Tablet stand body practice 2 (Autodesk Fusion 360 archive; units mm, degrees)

design "mm-Tablet stand body practice 2" references "haas minimill"
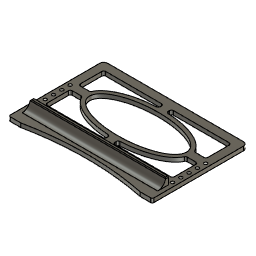
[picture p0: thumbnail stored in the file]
sketch "Sketch1" plane through (0, 0, 0) normal (0, 0, 1) x axis (1, 0, 0)
  line L1 (225.425, 0) -> (0, 0)
  line L2 (225.425, 149.225) -> (225.425, 0)
  line L3 (0, 149.225) -> (225.425, 149.225)
  line L4 (0, 0) -> (0, 149.225)
  point P1 (0, 0)
  point P2 (0, 0)
  point P3 (225.425, 0)
  point P5 (0, 149.225)
  horizontal L1
  vertical L2
  horizontal L3
  vertical L4
  coincident P1 P2
  dimension "d1" distance P2 P3 = 225.425
  dimension "d2" distance P2 P5 = 149.225
extrude "Extrude1" new body sketch "Sketch1" along normal blind 6.35
sketch "Sketch2" plane through (225.425, 0, 0) normal (1, 0, 0) x axis (0, 1, 0)
  line L1 (149.225, 0) -> (0, 0)
  line L2 (149.225, 6.35) -> (149.225, 0)
  line L3 (0, 6.35) -> (149.225, 6.35)
  line L4 (0, 0) -> (0, 6.35)
  line L5 (15.875, 6.35) -> (0, 6.35)
  line L6 (28.575, 6.35) -> (15.875, 6.35)
  line L7 (28.575, 17.907) -> (28.575, 6.35)
  line L8 (31.75, 17.907) -> (28.575, 17.907)
  line L9 (31.75, 6.35) -> (31.75, 17.907)
  line L10 (28.575, 6.35) -> (31.75, 6.35)
  line L11 (27.305, 6.35) -> (28.575, 6.35)
  line L12 (27.305, 16.637) -> (27.305, 6.35)
  line L13 (27.305, 16.637) -> (28.575, 17.907)
  line L14 (34.0111, 17.907) -> (28.575, 17.907)
  point P5 (0, 6.35)
  point P6 (0, 6.35)
  point P11 (31.75, 6.35)
  point P7 (15.875, 6.35)
  point P8 (28.575, 6.35)
  point P9 (28.575, 17.907)
  point P10 (31.75, 17.907)
  point P12 (27.305, 6.35)
  coincident P5 P6
  perpendicular L4 L5
  parallel L3 L6
  perpendicular L6 L7
  perpendicular L7 L8
  coincident L3 P11
  perpendicular L3 L9
  perpendicular L7 L11
  perpendicular L6 L12
  horizontal L14
  dimension "d5" distance P6 P7 = 15.875
  dimension "d6" distance P7 P8 = 12.7
  dimension "d8" distance P8 P9 = 11.557
  dimension "d9" distance P9 P10 = 3.175
  dimension "d10" distance P8 P12 = 1.27
  dimension "d11" angle L13 L14 = 135
extrude "Extrude2" add sketch "Sketch2" profile of L3 L6 L7 L8 L9 L10 L11 L12 L13 against normal blind 225.425
fillet "Fillet1" radius 12.7
sketch "Sketch3" plane through (0, 0, 6.35) normal (0, 0, 1) x axis (-1, 0, 0)
  line L1 (0, -14.8363) -> (-225.425, -14.8363)
  line L2 (0, 0) -> (0, -14.8363)
  line L3 (-225.425, 0) -> (0, 0)
  line L4 (-225.425, -14.8363) -> (-225.425, 0)
  line L5 (-19.05, 0) -> (0, 0)
  line L6 (-206.375, 0) -> (-225.425, 0)
  line L7 (-206.375, 0) -> (-19.05, 0)
  arc A1 centre (-112.7125, 457.2) radius 466.6953 clockwise from (-19.05, 0) to (-206.375, 0)
  point P4 (0, 0)
  point P6 (0, 0)
  point P5 (-225.425, 0)
  point P8 (-225.425, 0)
  point P7 (-19.05, 0)
  point P9 (-206.375, 0)
  point P10 (-112.7125, 457.2)
  coincident P4 P6
  perpendicular L2 L5
  coincident P5 P8
  perpendicular L4 L6
  dimension "d16" distance P6 P7 = 19.05
  dimension "d17" distance P8 P9 = 19.05
  dimension "d18" distance L3 P10 = 457.2
extrude "Extrude3" cut sketch "Sketch3" profile of L3 A1 L7 against normal blind 6.35
sketch "Sketch4" plane through (0, 0, 17.907) normal (0, 0, 1) x axis (-1, 0, 0)
  line L1 (-225.425, -31.75) -> (-225.425, -28.575)
  line L2 (0, -31.75) -> (-225.425, -31.75)
  line L3 (0, -28.575) -> (0, -31.75)
  line L4 (-225.425, -28.575) -> (0, -28.575)
  line L5 (-6.35, -31.75) -> (0, -31.75)
  line L6 (-6.35, -12.7) -> (-6.35, -31.75)
  line L7 (0, -12.7) -> (-6.35, -12.7)
  line L8 (0, -31.75) -> (0, -12.7)
  point P4 (0, -31.75)
  point P6 (0, -31.75)
  point P7 (-6.35, -31.75)
  point P9 (0, -12.7)
  horizontal L5
  vertical L6
  horizontal L7
  vertical L8
  coincident P4 P6
  dimension "d21" distance P6 P7 = 6.35
  dimension "d22" distance P6 P9 = 19.05
work_plane "WorkPlane1"
extrude "Extrude4" cut sketch "Sketch4" profile of L2 L3 L4 L5 L6 L7 L8 to an object
sketch "Sketch5" plane through (0, 0, 17.907) normal (0, 0, 1) x axis (-1, 0, 0)
  line L1 (-6.35, -28.575) -> (-6.35, -31.75)
  line L2 (-225.425, -28.575) -> (-6.35, -28.575)
  line L3 (-225.425, -31.75) -> (-225.425, -28.575)
  line L4 (-6.35, -31.75) -> (-225.425, -31.75)
  line L5 (-219.075, -31.75) -> (-225.425, -31.75)
  line L6 (-219.075, -12.7) -> (-219.075, -31.75)
  line L7 (-225.425, -12.7) -> (-219.075, -12.7)
  line L8 (-225.425, -31.75) -> (-225.425, -12.7)
  point P5 (-225.425, -31.75)
  point P6 (-225.425, -31.75)
  point P7 (-219.075, -31.75)
  point P9 (-225.425, -12.7)
  horizontal L5
  vertical L6
  horizontal L7
  vertical L8
  coincident P5 P6
  dimension "d25" distance P6 P7 = 6.35
  dimension "d26" distance P6 P9 = 19.05
extrude "Extrude5" cut sketch "Sketch5" profile of L2 L3 L4 L5 L6 L7 L8 to an object
chamfer "Chamfer1" distance 1.27
sketch "Sketch6" plane through (0, 0, 6.35) normal (0, 0, 1) x axis (-1, 0, 0)
  line L1 (-225.425, -149.225) -> (-225.425, 0)
  line L2 (0, -149.225) -> (-225.425, -149.225)
  line L3 (0, 0) -> (0, -149.225)
  line L4 (-19.05, 0) -> (0, 0)
  line L5 (-225.425, 0) -> (-206.375, 0)
  line L6 (-219.075, -14.8363) -> (-219.075, -31.75)
  line L7 (-6.35, -14.8363) -> (-219.075, -14.8363)
  line L8 (-6.35, -31.75) -> (-6.35, -14.8363)
  line L9 (-219.075, -31.75) -> (-6.35, -31.75)
  line L10 (-112.7125, -31.75) -> (-112.7125, -149.225)
  line L11 (-225.425, -90.4875) -> (-112.7125, -90.4875)
  curve K1 (-188.9125, -90.4875) -> (-36.5125, -90.4875)
  curve K2 (-112.7125, -122.2375) -> (-112.7125, -58.7375)
  arc A1 centre (-112.7125, 457.2) radius 466.6953 clockwise from (-19.05, 0) to (-206.375, 0)
  closed curve K3 centre (-112.7125, -90.4875)
  point P13 (-112.7125, -149.225)
  point P14 (-112.7125, -31.75)
  point P15 (-112.7125, -90.4875)
  point P18 (-36.5125, -90.4875)
  point P19 (-188.9125, -90.4875)
  point P20 (-112.7125, -58.7375)
  point P21 (-112.7125, -122.2375)
  point P17 (-112.7125, -90.4875)
  point P16 (-225.425, -90.4875)
  midpoint L2 P13
  midpoint L9 P14
  midpoint L10 P15
  perpendicular L10 L11
  coincident K3 P18
  coincident K3 P19
  coincident K3 P20
  coincident K3 P21
  coincident P15 P17
  perpendicular L10 K1
  coincident L1 P16
  dimension "d37" distance K3 = 152.4
  dimension "d38" = 31.75
extrude "Extrude6" cut sketch "Sketch6" profile of L10 L11 K3 no distance stored
sketch "Sketch7" plane through (0, 0, 6.35) normal (0, 0, 1) x axis (-1, 0, 0)
  line L1 (-212.725, -136.525) -> (-12.7, -136.525)
  line L2 (-212.725, -44.45) -> (-212.725, -136.525)
  line L3 (-12.7, -44.45) -> (-212.725, -44.45)
  line L4 (-12.7, -136.525) -> (-12.7, -44.45)
  line L5 (-225.425, -149.225) -> (-225.425, 0)
  line L6 (0, -149.225) -> (-225.425, -149.225)
  line L7 (0, 0) -> (0, -149.225)
  line L8 (-19.05, 0) -> (0, 0)
  line L9 (-225.425, 0) -> (-206.375, 0)
  line L10 (-219.075, -14.8363) -> (-219.075, -31.75)
  line L11 (-6.35, -14.8363) -> (-219.075, -14.8363)
  line L12 (-6.35, -31.75) -> (-6.35, -14.8363)
  line L13 (-219.075, -31.75) -> (-6.35, -31.75)
  line L14 (-106.3625, -90.4875) -> (-112.7125, -90.4875)
  line L15 (-112.7125, -44.45) -> (-112.7125, -90.4875)
  line L16 (-112.7125, -136.525) -> (-112.7125, -90.4875)
  line L17 (-106.3625, -84.1375) -> (-106.3625, -90.4875)
  line L18 (-106.3625, -44.45) -> (-106.3625, -52.5004)
  line L19 (-119.0625, -84.1375) -> (-119.0625, -90.4875)
  line L20 (-119.0625, -44.45) -> (-119.0625, -52.5004)
  line L21 (-106.3625, -122.1271) -> (-106.3625, -90.4875)
  line L22 (-106.3625, -136.525) -> (-106.3625, -128.4746)
  line L23 (-119.0625, -122.1271) -> (-119.0625, -90.4875)
  line L24 (-119.0625, -136.525) -> (-119.0625, -128.4746)
  line L25 (-119.0625, -84.1375) -> (-112.7125, -84.1375)
  line L26 (-212.725, -84.1375) -> (-194.1079, -84.1375)
  line L27 (-119.0625, -96.8375) -> (-112.7125, -96.8375)
  line L28 (-212.725, -96.8375) -> (-194.1079, -96.8375)
  line L29 (-119.0625, -90.4875) -> (-112.7125, -90.4875)
  line L30 (-195.2625, -90.4875) -> (-188.9125, -90.4875)
  line L31 (-38.0521, -84.1375) -> (-112.7125, -84.1375)
  line L32 (-12.7, -84.1375) -> (-31.3171, -84.1375)
  line L33 (-38.0521, -96.8375) -> (-112.7125, -96.8375)
  line L34 (-12.7, -96.8375) -> (-31.3171, -96.8375)
  closed curve K1 centre (-112.7125, -90.4875)
  arc A1 centre (-112.7125, 457.2) radius 466.6953 clockwise from (-19.05, 0) to (-206.375, 0)
  closed curve K2 centre (-112.7125, -90.4875)
  closed curve K3 centre (-112.7125, -90.4875)
  point P6 (-112.7125, -90.4875)
  point P20 (-112.7125, -90.4875)
  point P18 (-112.7125, -90.4875)
  point P21 (-112.7125, -90.4875)
  point P22 (-112.7125, -44.45)
  point P23 (-112.7125, -90.4875)
  point P24 (-112.7125, -136.525)
  point P39 (-106.3625, -84.1375)
  point P41 (-119.0625, -52.5004)
  point P42 (-106.3625, -52.5004)
  point P43 (-106.3625, -122.1271)
  point P44 (-106.3625, -128.4746)
  point P45 (-119.0625, -122.1271)
  point P46 (-119.0625, -128.4746)
  point P47 (-119.0625, -96.8375)
  point P48 (-194.1079, -96.8375)
  point P49 (-194.1079, -84.1375)
  point P50 (-188.9125, -90.4875)
  point P51 (-195.2625, -90.4875)
  point P52 (-38.0521, -84.1375)
  point P53 (-31.3171, -84.1375)
  point P54 (-38.0521, -96.8375)
  point P55 (-31.3171, -96.8375)
  horizontal L1
  vertical L2
  horizontal L3
  vertical L4
  coincident P6 P20
  perpendicular L2 L29
  coincident P18 P21
  midpoint L3 P22
  perpendicular L3 L15
  coincident P18 P23
  midpoint L1 P24
  coincident P39 L31
  collinear L17 L18
  collinear L19 L20
  coincident K3 P41
  coincident K3 P42
  coincident K1 P43
  coincident K3 P44
  collinear L21 L22
  coincident K1 P45
  coincident K3 P46
  collinear L23 L24
  collinear L25 L26
  coincident L23 P47
  collinear L27 L28
  coincident K3 P48
  coincident K3 P49
  coincident K1 P50
  collinear L29 L30
  coincident K3 P51
  coincident K1 P52
  coincident K3 P53
  collinear L31 L32
  coincident K1 P54
  coincident K3 P55
  collinear L33 L34
  dimension "d65" distance L1 L6 = 12.7
  dimension "d66" distance L2 L5 = 12.7 (= "d65")
  dimension "d67" distance L3 L13 = 12.7
  dimension "d68" = 38.1
extrude "Extrude7" cut sketch "Sketch7" profile of L1 L2 L3 L4 K3 L24 L22 L26 L32 L28 L34 L18 L20 no distance stored
fillet "Fillet2" radius 3
fillet "Fillet3" radius 3
hole "Hole1" HoleDepth 35.56 HoleDiameter 5.035 TipAngle 118 RefDim1 6.35 RefDim2 38.1
rectangular_pattern "R-Pattern1" uSpaceDistance -52.07 vSpaceDistance 212.725
fillet "Fillet4" radius 6
fillet "Fillet5" radius 2.5
fillet "Fillet6" radius 2.5
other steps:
thread "Thread1"

design "haas minimill"
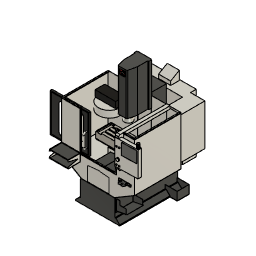
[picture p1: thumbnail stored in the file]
